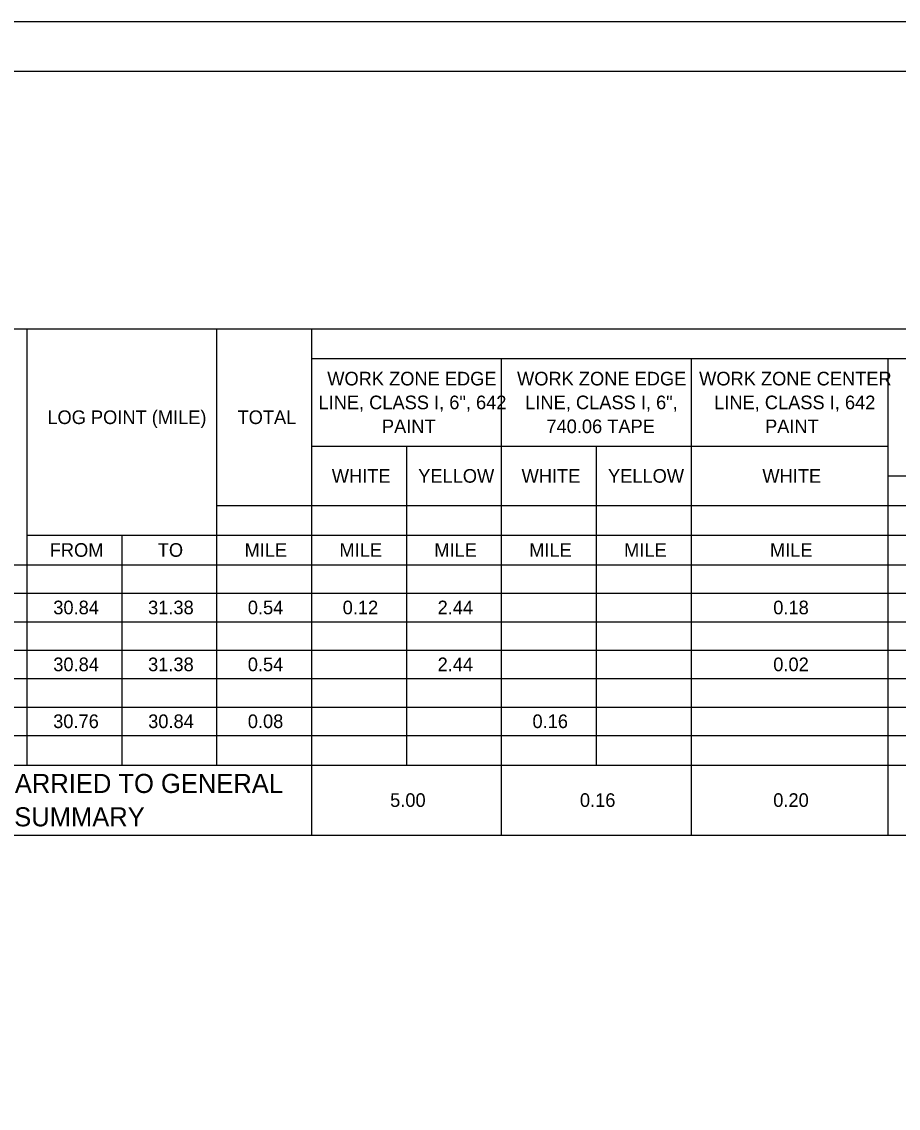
# Model space of a CAD drawing. Extents: x 0 to 34, y 0 to 22.
# Drawn here: x 7.75 to 16.62, y 11 to 22 of the extents above; entities that cross this region are included whole.
import ezdxf

# ---------------------------------------------------------------- set-up
doc = ezdxf.new("R2010")
doc.units = 0
for name, color, linetype in [('SH_Border', 7, 'Continuous'), ('SH_Cut_Line', 7, 'Continuous'), ('SH_Text', 7, 'Continuous')]:
    doc.layers.add(name, color=color, linetype=linetype)

msp = doc.modelspace()

# ---------------------------------------------------------------- linework, layer by layer
at = {"layer": 'SH_Border'}
msp.add_lwpolyline([(1.5, 21.5), (33.5, 21.5), (33.5, 0.5), (1.5, 0.5)], close=True, dxfattribs=at)
at = {"layer": 'SH_Cut_Line'}
msp.add_lwpolyline([(0, 0), (34, 0), (34, 22), (0, 22)], close=True, dxfattribs=at)
at = {"layer": 'SH_Text'}
for p, q in [((4.899, 18.89), (7.803, 18.89)), ((7.803, 18.89), (16.515, 18.89)), ((7.803, 18.89), (7.803, 17.402)), ((9.723, 18.89), (9.723, 17.402)), ((10.683, 18.89), (10.683, 17.402)), ((16.515, 18.89), (18.279, 18.89)), ((10.683, 18.59), (16.515, 18.59)), ((12.603, 18.59), (12.603, 17.402)), ((14.523, 18.59), (14.523, 17.402)), ((16.515, 18.59), (18.279, 18.59)), ((16.515, 18.59), (16.515, 17.402)), ((10.683, 17.702), (16.515, 17.702)), ((11.643, 17.702), (11.643, 17.402)), ((13.563, 17.702), (13.563, 17.402)), ((7.803, 17.402), (7.803, 16.214)), ((9.723, 17.402), (9.723, 16.214)), ((10.683, 17.402), (10.683, 16.214)), ((11.643, 17.402), (11.643, 16.214)), ((12.603, 17.402), (12.603, 16.214)), ((13.563, 17.402), (13.563, 16.214)), ((14.523, 17.402), (14.523, 16.214)), ((16.515, 17.402), (18.279, 17.402)), ((16.515, 17.402), (16.515, 16.214)), ((9.723, 17.102), (16.515, 17.102)), ((16.515, 17.102), (18.279, 17.102)), ((7.803, 16.802), (16.515, 16.802)), ((8.763, 16.802), (8.763, 16.214)), ((16.515, 16.802), (18.279, 16.802)), ((4.899, 16.502), (7.803, 16.502)), ((7.803, 16.502), (16.515, 16.502)), ((16.515, 16.502), (18.279, 16.502)), ((4.899, 16.214), (7.803, 16.214)), ((7.803, 16.214), (16.515, 16.214)), ((7.803, 16.214), (7.803, 15.926)), ((8.763, 16.214), (8.763, 15.926)), ((9.723, 16.214), (9.723, 15.926)), ((10.683, 16.214), (10.683, 15.926)), ((11.643, 16.214), (11.643, 15.926)), ((12.603, 16.214), (12.603, 15.926)), ((13.563, 16.214), (13.563, 15.926)), ((14.523, 16.214), (14.523, 15.926)), ((16.515, 16.214), (18.279, 16.214)), ((16.515, 16.214), (16.515, 15.926)), ((4.899, 15.926), (7.803, 15.926)), ((7.803, 15.926), (16.515, 15.926)), ((7.803, 15.926), (7.803, 15.638)), ((8.763, 15.926), (8.763, 15.638)), ((9.723, 15.926), (9.723, 15.638)), ((10.683, 15.926), (10.683, 15.638)), ((11.643, 15.926), (11.643, 15.638)), ((12.603, 15.926), (12.603, 15.638)), ((13.563, 15.926), (13.563, 15.638)), ((14.523, 15.926), (14.523, 15.638)), ((16.515, 15.926), (18.279, 15.926)), ((16.515, 15.926), (16.515, 15.638)), ((4.899, 15.638), (7.803, 15.638)), ((7.803, 15.638), (16.515, 15.638)), ((7.803, 15.638), (7.803, 14.474)), ((8.763, 15.638), (8.763, 14.474)), ((9.723, 15.638), (9.723, 14.474)), ((10.683, 15.638), (10.683, 13.766)), ((11.643, 15.638), (11.643, 14.474)), ((12.603, 15.638), (12.603, 13.766)), ((13.563, 15.638), (13.563, 14.474)), ((14.523, 15.638), (14.523, 13.766)), ((16.515, 15.638), (18.279, 15.638)), ((16.515, 15.638), (16.515, 13.766)), ((4.899, 15.35), (7.803, 15.35)), ((7.803, 15.35), (16.515, 15.35)), ((16.515, 15.35), (18.279, 15.35)), ((4.899, 15.062), (7.803, 15.062)), ((7.803, 15.062), (16.515, 15.062)), ((16.515, 15.062), (18.279, 15.062)), ((4.899, 14.774), (7.803, 14.774)), ((7.803, 14.774), (16.515, 14.774)), ((16.515, 14.774), (18.279, 14.774)), ((4.899, 14.474), (7.803, 14.474)), ((7.803, 14.474), (16.515, 14.474)), ((16.515, 14.474), (18.279, 14.474)), ((4.899, 13.766), (7.803, 13.766)), ((7.803, 13.766), (16.515, 13.766)), ((16.515, 13.766), (18.279, 13.766))]:
    msp.add_line(p, q, dxfattribs=at)

# ---------------------------------------------------------------- texts
for s, height, p in [('WORK ZONE EDGE ', 0.138, (10.843, 18.318)), ('WORK ZONE EDGE ', 0.138, (12.763, 18.318)), ('WORK ZONE CENTER ', 0.138, (14.605, 18.318)), ('LINE, CLASS I, 6", 642 ', 0.138, (10.754, 18.077)), ('LINE, CLASS I, 6", ', 0.138, (12.846, 18.077)), ('LINE, CLASS I, 642 ', 0.138, (14.757, 18.077)), ('LOG POINT (MILE)', 0.138, (8.011, 17.927)), ('TOTAL', 0.138, (9.935, 17.927)), ('PAINT', 0.138, (11.396, 17.835)), ('740.06 TAPE', 0.138, (13.06, 17.835)), ('PAINT', 0.138, (15.272, 17.835)), ('WHITE', 0.138, (10.889, 17.333)), ('YELLOW', 0.138, (11.763, 17.333)), ('WHITE', 0.138, (12.809, 17.333)), ('YELLOW', 0.138, (13.683, 17.333)), ('WHITE', 0.138, (15.245, 17.333)), ('FROM', 0.138, (8.035, 16.583)), ('TO', 0.138, (9.128, 16.583)), ('MILE', 0.138, (10.006, 16.583)), ('MILE', 0.138, (10.966, 16.583)), ('MILE', 0.138, (11.926, 16.583)), ('MILE', 0.138, (12.886, 16.583)), ('MILE', 0.138, (13.846, 16.583)), ('MILE', 0.138, (15.322, 16.583)), ('30.84', 0.138, (8.071, 16.001)), ('31.38', 0.138, (9.03, 16.001)), ('0.54', 0.138, (10.039, 16.001)), ('0.12', 0.138, (10.999, 16.001)), ('2.44', 0.138, (11.959, 16.001)), ('0.18', 0.138, (15.355, 16.001)), ('30.84', 0.138, (8.071, 15.425)), ('31.38', 0.138, (9.03, 15.425)), ('0.54', 0.138, (10.039, 15.425)), ('2.44', 0.138, (11.959, 15.425)), ('0.02', 0.138, (15.355, 15.425)), ('30.76', 0.138, (8.07, 14.849)), ('30.84', 0.138, (9.031, 14.849)), ('0.08', 0.138, (10.039, 14.849)), ('0.16', 0.138, (12.919, 14.849)), ('TOTALS CARRIED TO GENERAL ', 0.1932, (6.419, 14.192)), ('5.00', 0.138, (11.479, 14.051)), ('0.16', 0.138, (13.399, 14.051)), ('0.20', 0.138, (15.355, 14.051)), ('SUMMARY', 0.1932, (7.676, 13.854))]:
    msp.add_text(s, height=height, dxfattribs=at).set_placement(p)

doc.saveas('drawing.dxf')
